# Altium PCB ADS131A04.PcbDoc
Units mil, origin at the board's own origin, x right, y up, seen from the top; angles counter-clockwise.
Board outline 2190 x 1496.06 mil, 2 copper layers (Top Layer, Bottom Layer); 74 components, 47 nets, 208 pads, 279 vias.
Unrouted connection lines stored in the file: 46.
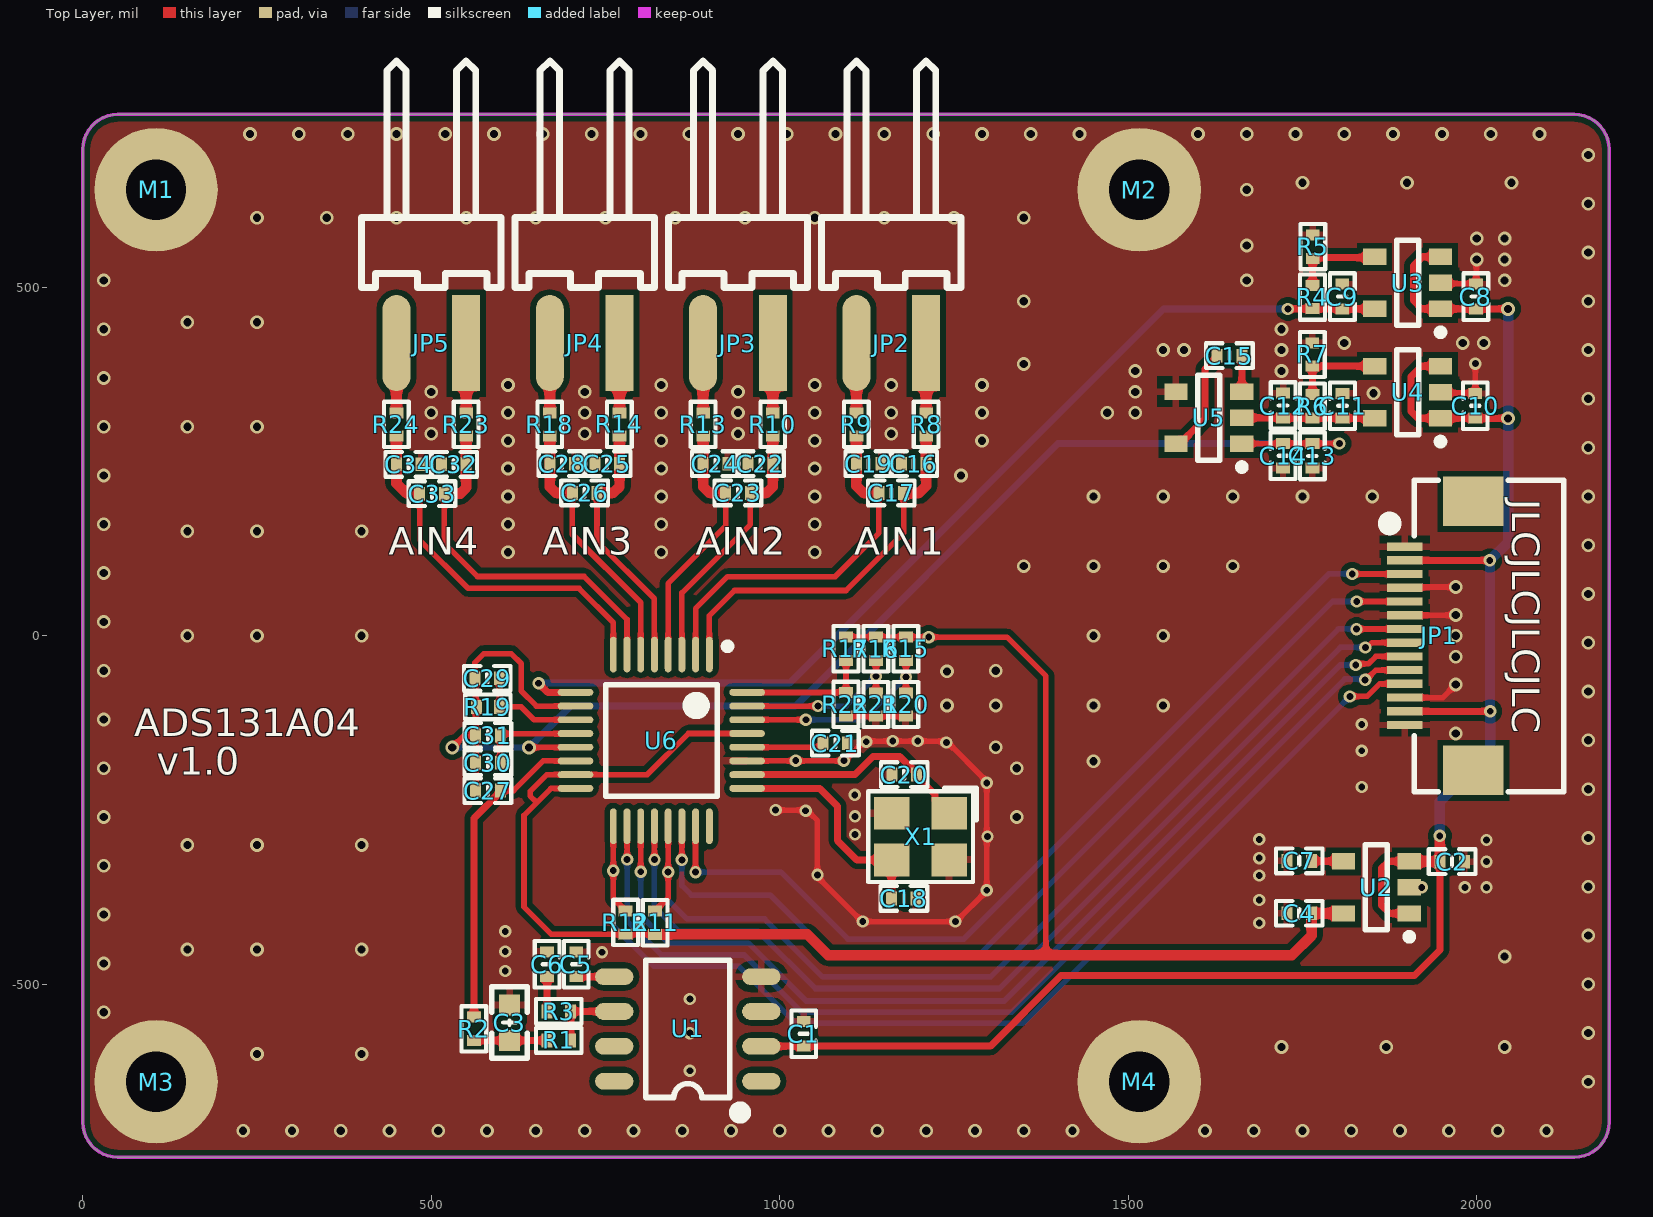
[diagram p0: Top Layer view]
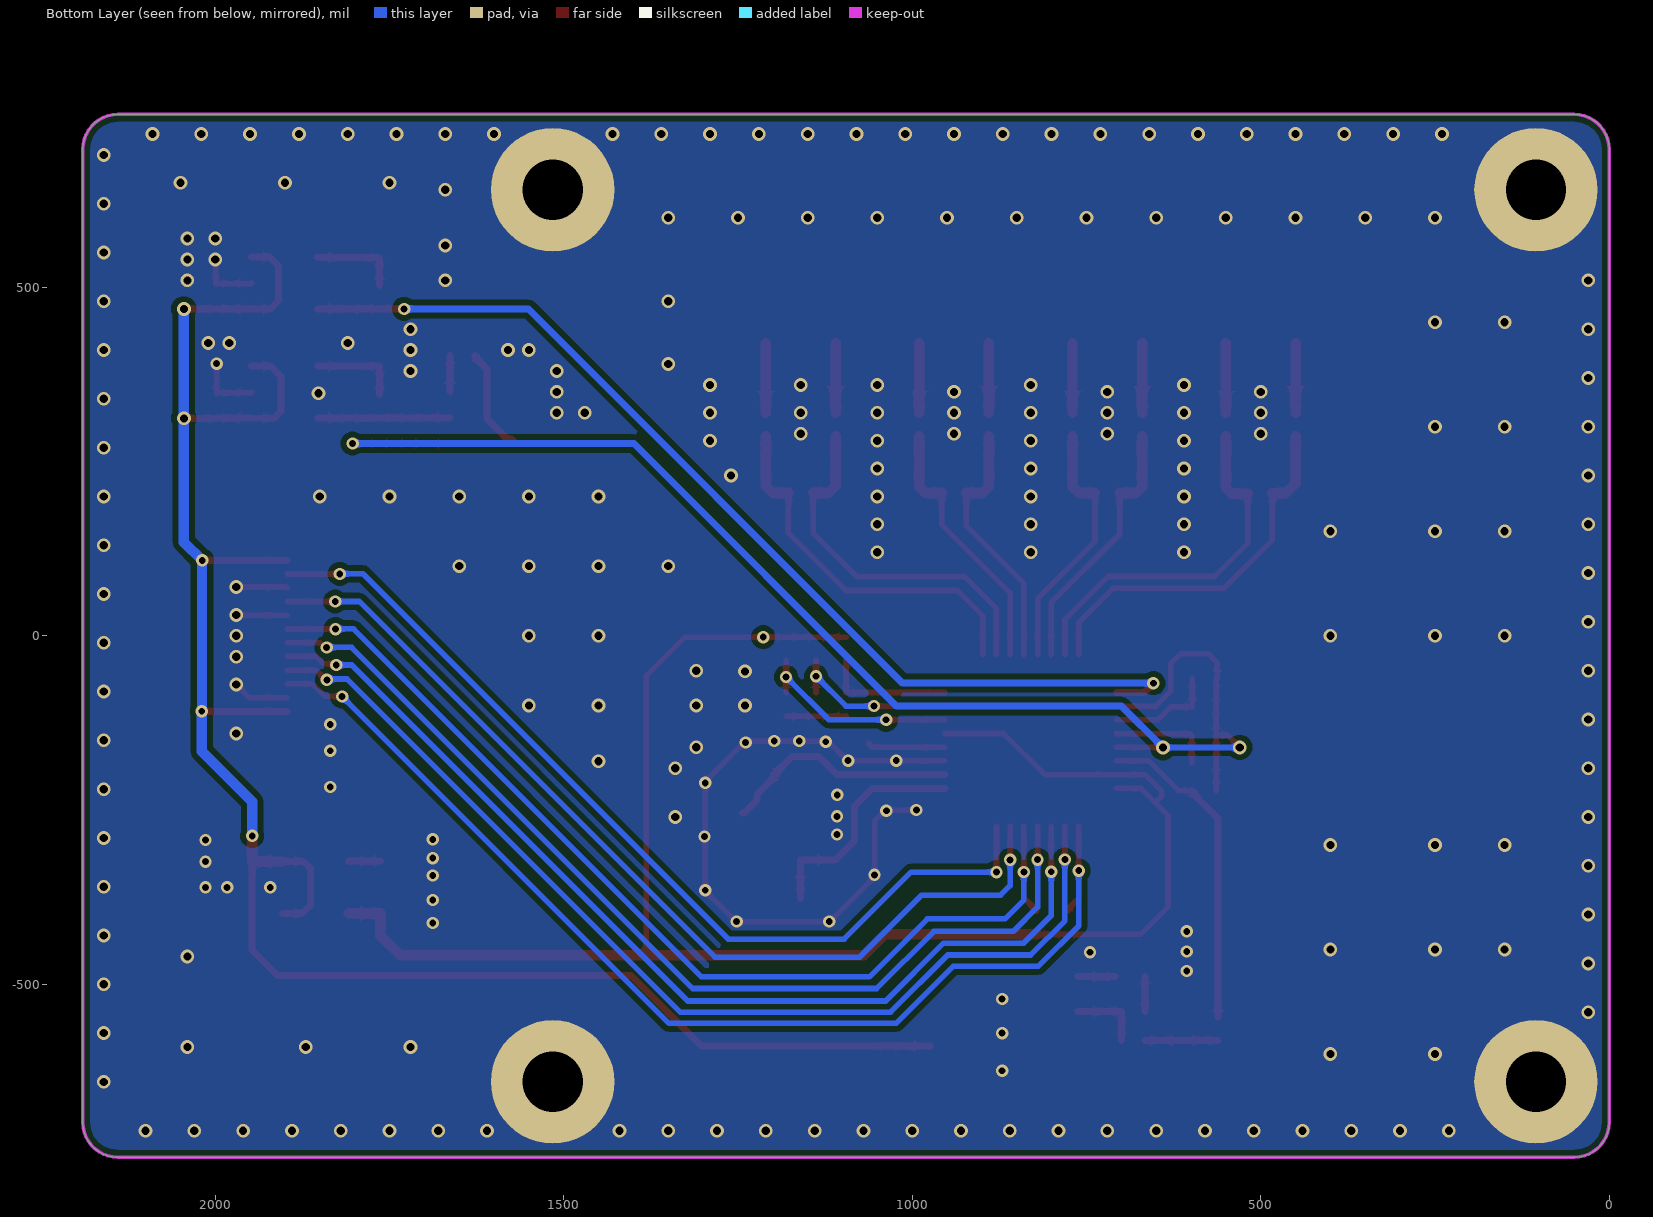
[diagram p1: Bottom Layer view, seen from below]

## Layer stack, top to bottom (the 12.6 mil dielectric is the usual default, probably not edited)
Top Solder: solder mask 0.4, Solder Resist, Dk 3.5
Top Layer: signal copper 1.4
Dielectric 1: dielectric 12.6, FR-4, Dk 4.8
Bottom Layer: signal copper 1.4
Bottom Solder: solder mask 0.4, Solder Resist, Dk 3.5

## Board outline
50,-748.03 cw(c50,-698.03) 0,-698.03 0,698.03 cw(c50,698.03) 50,748.03 2140,748.03 cw(c2140,698.03) 2190,698.03 2190,-698.03 cw(c2140,-698.03) 2140,-748.03

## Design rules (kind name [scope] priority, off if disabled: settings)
Clearance Clearance_1 [InPolygon] p1: gap=8 ignorepadtopadclearanceinfootprint=FALSE
Clearance [All] p2: gap=6 ignorepadtopadclearanceinfootprint=FALSE
MinimumSolderMaskSliver [All] p1: minsoldermaskwidth=0
PolygonConnect M2 [HasFootprint('M2')] p1: connectstyle=Direct reliefconductorwidth=10 reliefentries=4 polygonreliefangle="90 Angle" airgapwidth=10
PolygonConnect [All] p2: thpad.connectstyle=Relief thpad.reliefconductorwidth=10 thpad.reliefentries=4 thpad.polygonreliefangle="90 Angle" thpad.airgapwidth=10 smdpad.connectstyle=Relief smdpad.reliefconductorwidth=10 smdpad.reliefentries=4 smdpad.polygonreliefangle="90 Angle" smdpad.airgapwidth=10 via.connectstyle=Direct via.reliefconductorwidth=10 via.reliefentries=4 via.polygonreliefangle="90 Angle" via.airgapwidth=10
RoutingVias [All] p1: holewidth=9.84 width=17.72 viastyle="Through Hole" minholewidth=9.84 minwidth=17.72 maxholewidth=23.62 maxwidth=31.5
SilkToSilkClearance [All] p1: silktosilkclearance=0
SilkToSolderMaskClearance [IsPad] p1: minsilkscreentomaskgap=0 clearancetoexposedcopper=TRUE
SolderMaskExpansion [IsVia] p1: expansion=4 istentingtop=TRUE useseparateexpansions=TRUE expansionbottom=4 istentingbottom=TRUE
Width [All] p1: maxlimit=50 minlimit=6 preferedwidth=6
27 further rules are at their usual default settings.

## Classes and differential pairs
component class Power: C1 C2 C3 C4 C5 C6 C7 C8 C9 C10 C11 C12 C13 C14 C15 JP1 M1 M2 M3 M4 R1 R2 R3 R4 R5 R6 R7 U1 U2 U3 U4 U5
component class ADS131A04: C16 C17 C18 C19 C20 C21 C22 C23 C24 C25 C26 C27 C28 C29 C30 C31 C32 C33 C34 JP2 JP3 JP4 JP5 R8 R9 R10 R11 R12 R13 R14 R15 R16 R17 R18 R19 R20 R21 R22 R23 R24 U6 X1

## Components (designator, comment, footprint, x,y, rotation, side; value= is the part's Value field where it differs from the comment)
C1 "1uF" C0402_L 1034.42,-570.99 r270 top
C2 "1uF" C0402_L 1964.71,-324 r180 top
C3 "10uF" C0603_L 612.32,-555 r270 top
C4 "1uF" C0402_L 1745.29,-398 r0 top
C5 "1000pF" C0402_L 708,-471.29 r270 top
C6 "1uF" C0402_L 666,-471.29 r270 top
C7 "10nF" C0402_L 1745.29,-323 r0 top
C8 "1uF" C0402_L 1998.79,486.8 r270 top
C9 "1uF" C0402_L 1807.15,486.82 r270 top
C10 "1uF" C0402_L 1997.91,329.99 r270 top
C11 "1uF" C0402_L 1807.39,330.04 r270 top
C12 "0.01uF" C0402_L 1722.04,330.45 r270 top
C13 "1uF" C0402_L 1764.26,258.22 r90 top
C14 "0.01uF" C0402_L 1722.02,258.36 r90 top
C15 "1uF" C0402_L 1645.22,401.99 r180 top
C16 "100pF" C0402_L 1192.29,247 r0 top
C17 "4.7nF" C0402_L 1160,205 r0 top
C18 "30pF" C0402_L 1178.03,-376.82 r0 top
C19 "100pF" C0402_L 1127.72,247 r0 top
C20 "30pF" C0402_L 1178.5,-199.07 r180 top
C21 "1uF" C0402_L 1079.72,-154 r0 top
C22 "100pF" C0402_L 972.29,247 r0 top
C23 "4.7nF" C0402_L 940,205 r0 top
C24 "100pF" C0402_L 907.72,247 r0 top
C25 "100pF" C0402_L 752.29,247 r0 top
C26 "4.7nF" C0402_L 720,205 r0 top
C27 "1uF" C0402_L 581.28,-222 r180 top
C28 "100pF" C0402_L 687.72,247 r0 top
C29 "270nF" C0402_L 580.28,-61 r180 top
C30 "1uF" C0402_L 581.28,-182 r180 top
C31 "0.1uF" C0402_L 581.28,-143 r180 top
C32 "100pF" C0402_L 532.29,246 r0 top
C33 "4.7nF" C0402_L 501,204 r0 top
C34 "100pF" C0402_L 467.72,246 r0 top
JP1 "HDR-1X14" FPC0.5-WT-14P 1995,0 r270 top
JP2 "HDR-1X2" HDR2.54-WS-2P 1160,420 r180 top
JP3 "HDR-1X2" HDR2.54-WS-2P 940,420 r180 top
JP4 "HDR-1X2" HDR2.54-WS-2P 720,420 r180 top
JP5 "HDR-1X2" HDR2.54-WS-2P 500,420 r180 top
M1 "M2" M2 105,640 r0 top
M2 "M2" M2 1515.94,640 r0 top
M3 "M2" M2 105,-640 r0 top
M4 "M2" M2 1515.94,-640 r0 top
R1 "100R" R0402_L 682.91,-580.61 r180 top
R2 "NC/0R" R0402_L 561.24,-563.85 r90 top
R3 "1R" R0402_L 682.84,-538.97 r0 top
R4 "340K/1%" R0402_L 1764.33,486.07 r270 top
R5 "160K/1%" R0402_L 1764.8,558.43 r90 top
R6 "340K/1%" R0402_L 1764.19,329.37 r270 top
R7 "160K/1%" R0402_L 1764.15,403.66 r90 top
R8 "100R" R0402_L 1210,303.27 r270 top
R9 "100R" R0402_L 1110,303.27 r270 top
R10 "100R" R0402_L 989.98,303.27 r270 top
R11 "100K" R0402_L 821.02,-411.64 r270 top
R12 "100K" R0402_L 778.71,-411.26 r270 top
R13 "100R" R0402_L 890,303.27 r270 top
R14 "100R" R0402_L 770,303.27 r270 top
R15 "NC/0R" R0402_L 1181,-18.54 r90 top
R16 "NC/0R" R0402_L 1138,-18.54 r90 top
R17 "NC/0R" R0402_L 1095,-18.54 r90 top
R18 "100R" R0402_L 670,303.27 r270 top
R19 "NC/0R" R0402_L 581.27,-102 r180 top
R20 "NC/0R" R0402_L 1181,-98.54 r90 top
R21 "NC/0R" R0402_L 1138,-98.54 r90 top
R22 "NC/0R" R0402_L 1095,-98.27 r90 top
R23 "100R" R0402_L 550,303.27 r270 top
R24 "100R" R0402_L 450,303.27 r270 top
U1 "REF5025AIDR" SOIC-8L 868,-564 r180 top
U2 "LP2992-3.3" SOT23-5L 1856,-361 r180 top
U3 "SGM2036" SOT23-5L 1900.76,506.4 r180 top
U4 "SGM2036" SOT23-5L 1900.76,349.6 r180 top
U5 "TPS60403" SOT23-5L 1615.69,312.99 r180 top
U6 "ADS131A04" "TQFP32 5x5_L" 830,-150 r180 top
X1 "16.384MHz" XTAL-3225-4P 1202,-288 r180 top

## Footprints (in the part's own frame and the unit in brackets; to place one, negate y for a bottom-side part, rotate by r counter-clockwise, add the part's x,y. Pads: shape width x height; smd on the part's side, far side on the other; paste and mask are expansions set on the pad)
C0402_L [mm] "无极性贴片电容"
  rect 0.4x0.5 smd: 1(-0.45,0) 2(0.45,0)
  silkscreen extent -0.85,-0.45 0.85,0.45, body extent -0.5,-0.26 0.5,0.26, height 0.54
C0603_L [mil] "无极性贴片电容"
  rect 30x30 smd: 1(-25.59,0) 2(25.59,0)
  silkscreen extent -51,-26 51,26, body extent -31,-16 32,16, height 33
FPC0.5-WT-14P [mm] "长：11.2mm，宽：5.2mm，高：2mm"
  rect 1.8x2.2 smd: 0(-4.9,0) 0(4.9,0)
  rect 0.3x1.3 smd: 1(-3.25,-2.497) 2(-2.75,-2.497) 3(-2.25,-2.497) 4(-1.75,-2.497) 5(-1.25,-2.497) 6(-0.75,-2.497) 7(-0.25,-2.497) 8(0.25,-2.497) 9(0.75,-2.497) 10(1.25,-2.497) 11(1.75,-2.497) 12(2.25,-2.497) 13(2.75,-2.497) 14(3.25,-2.497)
  silkscreen extent -5.68,-3.23 5.68,3.3, body extent -5.6,-2.85 5.6,3.15, height 2
HDR2.54-WS-2P [mm] "2P卧式贴片排针2.54"
  rect 1.02x3.5 smd: 1(-1.27,0)
  oval 1.02x3.5 smd: 2(1.27,0)
  silkscreen extent -2.54,-10.29 2.54,-2.03, body extent -2.54,-10.34 2.54,0.76, height 2.59
M2 [mm]
  round 4.5 hole 2.2: 1(0,0)
R0402_L [mm] "1/16W贴片电阻"
  rect 0.4x0.5 smd: 1(-0.425,0) 2(0.425,0)
  silkscreen extent -0.82,-0.45 0.83,0.45, body extent -0.5,-0.25 0.5,0.25, height 0.3
SOIC-8L [mm] "封装库来自淘宝卖家 ID：黄晶宝石，其他均为盗版"
  oval 1.397x0.61 smd: 1(-2.68,1.905) 2(-2.68,0.635) 3(-2.68,-0.635) 4(-2.68,-1.905) 5(2.68,-1.905) 6(2.68,-0.635) 7(2.68,0.635) 8(2.68,1.905)
  silkscreen extent -2.06,-2.5 1.52,3.2, body extent -3,-2.5 3,2.5, height 1.9
SOT23-5L [mm] "SOT23, 5-Leads, Body 2.9x1.6mm, Pitch 0.95mm, IPC High Density"
  rect 0.85x0.6 smd: 1(-1.2,0.95) 2(-1.2,0) 3(-1.2,-0.95) 4(1.2,-0.95) 5(1.2,0.95)
  silkscreen extent -1.33,-1.55 0.4,1.92, body extent -1.4,-1.5 1.4,1.5, height 1.15
"TQFP32 5x5_L" [mm] "32脚，体宽：5x5mm, 脚距：0.5mm          淘宝ID:黄晶宝石"
  oval 0.25x1.3 smd: 1(-1.75,-3.127) 2(-1.25,-3.127) 3(-0.75,-3.127) 4(-0.25,-3.127) 5(0.25,-3.127) 6(0.75,-3.127) 7(1.25,-3.127) 8(1.75,-3.127) 17(1.75,3.127) 18(1.25,3.127) 19(0.75,3.127) 20(0.25,3.127) 21(-0.25,3.127) 22(-0.75,3.127) 23(-1.25,3.127) 24(-1.75,3.127)
  oval 1.3x0.25 smd: 9(3.127,-1.75) 10(3.127,-1.25) 11(3.127,-0.75) 12(3.127,-0.25) 13(3.127,0.25) 14(3.127,0.75) 15(3.127,1.25) 16(3.127,1.75) 25(-3.127,1.75) 26(-3.127,1.25) 27(-3.127,0.75) 28(-3.127,0.25) 29(-3.127,-0.25) 30(-3.127,-0.75) 31(-3.127,-1.25) 32(-3.127,-1.75)
  silkscreen extent -2.54,-3.55 2.03,2.03, body extent -3.5,-3.5 3.5,3.5, height 1.05
XTAL-3225-4P [mm] "3.2*2.5*0.7mm(长宽高)                             淘宝ID:黄晶宝石"
  rect 1.3x1.2 smd: 1(-1.05,-0.85) 2(1.05,-0.85) 3(1.05,0.85) 4(-1.05,0.85)
  silkscreen extent -2.03,-1.75 1.91,1.65, body extent -1.6,-1.25 1.6,1.25, height 0.7

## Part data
C1 C2 C3 C4 C5 C6 C7 C8 C9 C10 C11 C12 C13 C14 C15 C16 C17 C18 C19 C20 C21 C22 C23 C24 C25 C26 C27 C28 C29 C30 C31 C32 C33 C34: library part C, "贴片电容"
JP1: library part "Header 14", "14P接插件"
JP2 JP3 JP4 JP5: library part "Header 2", "2P接插件"
M1 M2 M3 M4: library part M2系列, "M2孔支撑柱"
R1 R2 R3 R4 R5 R6 R7 R8 R9 R10 R11 R12 R13 R14 R15 R16 R17 R18 R19 R20 R21 R22 R23 R24: library part R, "贴片电阻"
U1: "3uVpp/V噪声 3ppm/℃漂移 电压基准 0.05%"
U2: library part LP2992
U3 U4: "可调LDO"
U5: library part TPS6040x, "非稳压60mA电荷泵电压逆变器"
U6: "4通道差分24位ADC"
X1: library part XTAL-4P, "4脚无源晶振(谐振器）"

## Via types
v1: diameter 19.68, hole 11.81, Top Layer to Bottom Layer, tented both sides, 216 vias
v2: diameter 17.72, hole 9.84, Top Layer to Bottom Layer, tented both sides, 63 vias

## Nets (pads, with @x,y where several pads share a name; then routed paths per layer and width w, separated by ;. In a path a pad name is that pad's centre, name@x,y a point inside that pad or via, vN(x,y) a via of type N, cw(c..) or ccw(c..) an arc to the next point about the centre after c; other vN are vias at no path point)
+2V5: C9.2 R4.2 U3.5 U6.9 | length 1480.5
  Top Layer w10: v2(654,-68) 667.1,-81.1 U6.9 ; v2(1729,469) 1729.17,469.17 1764.16,469.17 R4.2 1764.45,469.22 1807.03,469.22 C9.2 1807.2,469.05 1853.46,469.05 U3.5
  Bottom Layer w10: v2(654,-68) 1013.78,-68 1550.78,469 v2(1729,469)
-2V5: C13.2 C14.2 C27.2 C29.2 C30.2 C31.2 R19.2 U5.1 U6.10 U6.13 | length 2090.2
  Top Layer w8: v1(530.16,-160.16) 547.8,-142.51 C31.2@564.05,-142.51 ; C27.2 C30.2 C31.2 C31.2@564.05,-142.51 ; v1(640.16,-160.35) 640.41,-160.1 706.63,-160.1 U6.13 ; U6.10 650.79,-100.79 629,-79 629,-40 614.82,-25.82 575.13,-25.82 562.57,-38.38 C29.2 563.55,-61.98 563.55,-101.02 R19.2 564.05,-102.48 C31.2@564.05,-142.51 ; U5.1 1663.18,275.83 1721.78,275.83 C14.2 1722.09,276 1764.2,276 C13.2 v2(1802.93,275.93)
  Bottom Layer w8: v1(530.16,-160.16) 530.25,-160.26 640.06,-160.26 v1(640.16,-160.35)
  Bottom Layer w10: v1(640.16,-160.35) 699.51,-101 1022.27,-101 1399.21,275.93 v2(1802.93,275.93)
ADS_CS: JP1.3 U6.23 | length 1340.8
  Top Layer w8: v2(879,-339) 879.11,-338.89 879.11,-273.22 U6.23 ; v2(1821.47,88.79) 1821.57,88.69 1896.59,88.69 JP1.3
  Bottom Layer w8: v2(879,-339) 1001.68,-339 1097.8,-435.12 1264,-435.12 1788.12,89 1821.26,89 v2(1821.47,88.79)
ADS_DIN: JP1.8 U6.20 | length 1446.5
  Top Layer w8: v2(820.16,-321.16) U6.20 ; v2(1840.18,-16.7) 1842.81,-16.7 1849.67,-9.84 JP1.8
  Bottom Layer w8: v2(820.16,-321.16) 820.16,-389.16 855,-424 969,-424 1051,-506 1315,-506 1804.3,-16.7 v2(1840.18,-16.7)
ADS_DONE: JP1.10 U6.18 | length 1510.3
  Top Layer w8: U6.18 781,-273.32 780.89,-273.43 780.89,-320.89 v2(781,-321) ; v2(1839.82,-63.18) 1841.38,-63.18 1855.35,-49.21 JP1.10
  Bottom Layer w8: v2(781,-321) 781,-409 830,-458 949,-458 1031,-540 1333,-540 1811,-62 1838.64,-62 v2(1839.82,-63.18)
ADS_DOUT: JP1.7 R11.1 U6.21 | length 1480.3
  Top Layer w8: R11.1 822.99,-394.9 826.87,-391.03 826.87,-389.06 839.84,-376.08 v2(839.84,-338.84) U6.21 ; v2(1827.49,9.67) 1827.58,9.76 1896.61,9.76 JP1.7
  Bottom Layer w8: v2(839.84,-338.84) 839.84,-378.94 867.03,-406.12 978.31,-406.12 1061.49,-489.3 1302.5,-489.3 1801.64,9.84 1827.32,9.84 v2(1827.49,9.67)
ADS_DRDY: JP1.9 U6.19 | length 1480.2
  Top Layer w8: v2(800.47,-338.47) U6.19 ; v2(1826.46,-41.91) 1828.32,-40.05 1844.71,-40.05 1855.24,-29.53 JP1.9
  Bottom Layer w8: v2(800.47,-338.47) 800.47,-401.47 840,-441 955,-441 1038,-524 1322,-524 1804.09,-41.91 v2(1826.46,-41.91)
ADS_RESET: JP1.11 R12.1 U6.17 | length 1604.2
  Top Layer w8: U6.17 v2(761.1,-336.9) 761.1,-376.92 772.87,-388.69 772.87,-390.66 776.74,-394.53 R12.1 ; v2(1818,-87) 1842.66,-87 1860.66,-69.01 JP1.11@1896.58,-69.01
  Bottom Layer w8: v2(761.1,-336.9) 761.1,-416.1 819,-474 941,-474 1023,-556 1349,-556 v2(1818,-87)
ADS_SCLK: JP1.5 U6.22 | length 1376.5
  Top Layer w8: v2(859.53,-321.53) U6.22 ; v2(1827.86,49.3) v2(1827.86,49.3) 1896.65,49.25 JP1.5
  Bottom Layer w8: v2(859.53,-321.53) 859.53,-358.53 873.1,-372.09 986.28,-372.09 1075.29,-461.1 1282.91,-461.1 1793.31,49.3 v2(1827.86,49.3)
AIN1N: C16.2 C17.2 R8.2 U6.1 | length 549.1
  Top Layer w8: U6.1 898.9,28.9 935,65 1095,65 1177.71,147.71 C17.2
  Top Layer w15: C17.2 1200,205 1210,215 C16.2 R8.2
AIN1P: C17.1 C19.1 R9.2 U6.2 | length 539.3
  Top Layer w8: U6.2 879.21,39.21 925,85 1079.54,85 1142.28,147.74 C17.1
  Top Layer w15: R9.2 C19.1 1110,215 1120,205 C17.1
AIN2N: C22.2 C23.2 R10.2 U6.3 | length 381.2
  Top Layer w8: U6.3 859.53,61.53 957.71,159.71 C23.2
  Top Layer w15: C23.2 981.2,205 989.99,213.78 C22.2 R10.2
AIN2P: C23.1 C24.1 R13.2 U6.4 | length 374.6
  Top Layer w8: U6.4 839.84,74.84 922.28,157.28 C23.1
  Top Layer w15: R13.2 C24.1 890,214 899,205 C23.1
AIN3N: C25.2 C26.2 R14.2 U6.5 | length 374.6
  Top Layer w8: C26.2 737.71,135.59 820.16,53.14 U6.5
  Top Layer w15: C26.2 761,205 770,214 C25.2 R14.2
AIN3P: C26.1 C28.1 R18.2 U6.6 | length 381.2
  Top Layer w8: C26.1 702.28,145.72 800.47,47.53 U6.6
  Top Layer w15: R18.2 670,213.79 678.79,205 C26.1
AIN4N: C32.2 C33.2 R23.2 U6.7 | length 537.7
  Top Layer w8: C33.2 518.71,132.75 566.32,85.14 719.17,85.14 780.79,23.53 U6.7
  Top Layer w15: C33.2 541.21,204 550,212.78 C32.2 R23.2
AIN4P: C33.1 C34.1 R24.2 U6.8 | length 546.3
  Top Layer w8: C33.1 483.28,137.72 553,68 712,68 761.1,18.9 U6.8
  Top Layer w15: R24.2 450,219 464.37,204.63 482.91,204.63 483.28,204.25 C33.1
GND: C1.1 C2.1 C3.1 C4.1 C5.1 C6.1 C7.1 C8.1 C9.1 C10.1 C11.1 C12.1 C13.1 C14.1 C16.1 C18.2 C19.2 C20.2 C21.2 C22.1 C24.2 C25.1 C28.2 C32.1 C34.2 JP1.1 JP1.4 JP1.6 JP1.12 JP1.14 M1.1 M2.1 M3.1 M4.1 R5.2 R7.2 R20.1 R21.1 R22.1 U1.4 U2.2 U3.2 U4.2 U5.4 U6.27 X1.2 X1.4 | length 1467.2
  Top Layer w8: U6.27 1092.47,-179.53 1121,-151 1239,-151 1297,-209 1297,-366 1253,-410 1118,-410 1054,-346 1054,-265 1039,-250 v2(994,-250) ; R22.1 1095.13,-115.13 1137.87,-115.13 R21.1 R20.1 ; JP1.12 1951.42,-88.58 v1(1970,-70) ; JP1.6 1969.53,29.53 v1(1970,30) ; JP1.4 1897.79,70 v1(1970,70) ; U4.2 1948.95,348.65 1996.96,348.65 C10.1 1997.96,347.76 v2(1998.01,390.6) v2(1998.01,390.6) ; U3.2 1948.94,505.46 1997.84,505.46 C8.1 1999.39,505.12 1999.39,539.39 v1(2000,540)
  other v1: 230,-710 300,-710 370,-710 440,-710 510,-710 580,-710 650,-710 720,-710 790,-710 860,-710 930,-710 1000,-710 1070,-710 1140,-710 1210,-710 1280,-710 1350,-710 1420,-710 1610,-710 1680,-710 1750,-710 1820,-710 1890,-710 1960,-710 2030,-710 2100,-710 2160,-640 250,-600 400,-600 1720,-590 1870,-590 2040,-590 2160,-570 30,-540 2160,-500 30,-470 2040,-460 150,-450 250,-450 400,-450 2160,-430 30,-400 2160,-360 30,-330 150,-300 250,-300 400,-300 2160,-290 30,-260 1340,-260 2160,-220 30,-190 1340,-190 1450,-180 1310,-160 2160,-150 1970,-140 30,-120 1240,-100 1310,-100 1450,-100 1550,-100 2160,-80 1240,-51 30,-50 1310,-50 1970,-30 2160,-10 150,0 250,0 400,0 1450,0 1550,0 1970,0 30,20 2160,60 30,90 1350,100 1450,100 1550,100 1650,100 610,120 830,120 1050,120 2160,130 150,150 250,150 400,150 30,160 610,160 830,160 1050,160 610,200 830,200 1050,200 1450,200 1550,200 1650,200 1750,200 1850,200 2160,200 30,230 1260,230 610,240 830,240 1050,240 2160,270 610,280 830,280 1050,280 1290,280 500,290 720,290 940,290 1160,290 30,300 150,300 250,300 500,320 610,320 720,320 830,320 940,320 1050,320 1160,320 1290,320 1470,320 1510,320 2160,340 1852,348 500,350 720,350 940,350 1510,350 610,360 830,360 1050,360 1160,360 1290,360 30,370 1510,380 1720,380 1350,390 1550,410 1580,410 1720,410 2160,410 1810,420 1980,420 2010,420 30,440 1720,440 150,450 250,450 1350,480 2160,480 30,510 1670,510 2040,510 2040,540 2160,550 1670,560 2000,570 2040,570 250,600 350,600 450,600 550,600 650,600 750,600 850,600 950,600 1050,600 1150,600 1250,600 1350,600 2160,620 1670,640 1750,650 1900,650 2050,650 2160,690 240,720 310,720 380,720 450,720 520,720 590,720 660,720 730,720 800,720 870,720 940,720 1010,720 1080,720 1150,720 1220,720 1290,720 1360,720 1430,720 1600,720 1670,720 1740,720 1810,720 1880,720 1950,720 2020,720 2090,720
  other v2: 871,-624 871,-570 871,-521 606,-481 745,-454 606,-453 606,-424 1688,-412 1119,-410 1252,-410 1688,-379 1297,-365 1921,-361 1983,-361 2014,-361 1688,-344 1054,-343 2014,-324 1688,-319 2014,-293 1688,-292 1298,-288 1108,-285 1108,-259 1037,-251 1107.56,-228.26 1835,-217 1297,-211 1023,-179 1092,-179 1835,-165 1239,-153 1124,-152 1162,-151 1198,-151 1835,-127
M0: R15.1 R20.2 U6.30 | length 299.9
  Top Layer w8: U6.30 v2(1037.47,-120.47) ; R20.2 v2(1181,-59) R15.1
  Bottom Layer w8: v2(1037.47,-120.47) 1119.53,-120.47 v2(1181,-59)
M1: R16.1 R21.2 U6.31 | length 249.1
  Top Layer w8: U6.31 v2(1054.79,-100.79) ; R21.2 v2(1138,-58) R16.1
  Bottom Layer w8: v2(1054.79,-100.79) 1095.21,-100.79 v2(1138,-58)
M2: R17.1 R22.2 U6.32 | length 188.3
  Top Layer w8: U6.32 953.33,-81.32 1094.78,-81.32 R22.2 R17.1
NetC3_2: C3.2 R1.2 R2.1 | length 105
  Top Layer w10: R2.1 C3.2 ; C3.2 R1.2
NetC5_2: C5.2 U1.5 | length 54.5
  Top Layer w10: C5.2 U1.5
NetC6_2: C6.2 R3.1 | length 50
  Top Layer w10: C6.2 666.05,-489.05 666.05,-538.92 R3.1
NetC7_2: C7.2 U2.4 | length 46
  Top Layer w10: C7.2 1763.3,-323.3 1808.46,-323.3 U2.4
NetC15_1: C15.1 U5.3 | length 51.6
  Top Layer w10: U5.3 C15.1
NetC15_2: C15.2 U5.5 | length 154.2
  Top Layer w10: U5.5 1575.26,282.39 1580.94,282.39 1610,311.46 1610,382.51 1627.51,400.02 C15.2
NetC21_1: C21.1 U6.28 | length 112.5
  Top Layer w8: U6.28 1058.13,-159.84 1062,-155.97 C21.1
NetC29_1: C29.1 R19.1 U6.11 | length 157.5
  Top Layer w8: C29.1 R19.1 629,-102 647.47,-120.47 U6.11
NetC30_1: C30.1 C31.1 U6.12 | length 148.1
  Top Layer w8: C30.1 C31.1 601.49,-140.51 706.54,-140.51 U6.12
NetJP2_1: JP2.1 R8.1 | length 100
  Top Layer w15: R8.1 JP2.1
NetJP2_2: JP2.2 R9.1 | length 100
  Top Layer w15: R9.1 JP2.2
NetJP3_1: JP3.1 R10.1 | length 100
  Top Layer w15: R10.1 JP3.1
NetJP3_2: JP3.2 R13.1 | length 100
  Top Layer w15: R13.1 JP3.2
NetJP4_1: JP4.1 R14.1 | length 100
  Top Layer w15: R14.1 JP4.1
NetJP4_2: JP4.2 R18.1 | length 100
  Top Layer w15: R18.1 JP4.2
NetJP5_1: JP5.1 R23.1 | length 100
  Top Layer w15: R23.1 JP5.1
NetJP5_2: JP5.2 R24.1 | length 100
  Top Layer w15: R24.1 JP5.2
NetR1_1: R1.1 R3.2 U1.6 | length 104.6
  Top Layer w10: R1.1 R1.1 R3.2 U1.6
NetR4_1: R4.1 R5.1 U3.4 | length 128.7
  Top Layer w10: R4.1 1764.57,503.03 1764.57,541.47 R5.1 1765.85,542.75 1852.46,542.75 U3.4
NetR6_1: R6.1 R7.1 U4.4 | length 130.2
  Top Layer w10: R6.1 R7.1@1764.17,386.91 ; R7.1 1764.19,386.96 U4.4 U4.4
VCC_2V5: C11.2 C12.2 R6.2 U4.5 U5.2 | length 190.9
  Top Layer w10: U5.2 1663.06,312.86 1721.91,312.86 C12.2 1722.08,312.69 1764.15,312.69 R6.2 1764.35,312.48 1807.23,312.48 C11.2 1807.45,312.26 1853.45,312.26 U4.5
VCC_3V3: C4.2 R11.2 R12.2 R15.2 R16.2 R17.2 U2.5 U6.15 U6.16 U6.29 | length 2586.9
  Top Layer w8: 650.71,-238.76 641.79,-229.84 641.79,-223.21 665.79,-199.21 U6.15 809.79,-199.21 868.84,-140.16 U6.29 ; 671.7,-218.9 633,-257.6 633,-389 672.37,-428.37 R11.2 820.84,-428.18 778.9,-428.18 R12.2 ; 672.5,-218.9 U6.16 ; R17.2 R16.2 R15.2 v2(1213.8,-1.8) 1325.8,-1.8 1381.72,-57.72 1381.72,-458.34 ; C4.2 C4.2@1763.2,-398.2 ; U2.5@1808.56,-398.2 U2.5
  Top Layer w15: R11.2 1039.37,-428.37 1069.34,-458.34 1381.72,-458.34 1734.66,-458.34 1763,-430 C4.2 ; C4.2@1763.2,-398.2 U2.5@1808.56,-398.2
VCC_5V: C1.2 C2.2 C8.2 C10.2 JP1.2 JP1.13 U1.2 U2.1 U2.3 U3.1 U3.3 U4.1 U4.3 | length 2899.1
  Top Layer w10: U1.2 973.66,-588.85 C1.2@1034.26,-588.85 ; C1.2 C1.2@1034.26,-588.85 ; JP1.13 v2(2019.32,-108.27) ; JP1.2 v2(2018.73,108.27) ; U2.1 1875.4,-398.4 1863,-386 1863,-334 1873.4,-323.6 U2.3 U2.3@1903.44,-323.8 ; C2.2@1946.8,-323.8 C2.2 1947,-450.83 1910.39,-487.44 1403.56,-487.44 1302.15,-588.85 C1.2@1034.26,-588.85 ; U4.3 1921,387 1906,372 1906,322 1915.8,312.2 U4.1 U4.1 1997.86,312.24 C10.2 1998.04,312.14 2044.86,312.14 v1(2045,312) ; U3.3 1921.8,543.8 1909,531 1909,481 1921,469 U3.1 U3.1 1998.74,469.04 C8.2 1998.82,469.04 v1(2045,469) v1(2045,469)
  Top Layer w15: U2.3@1903.44,-323.8 C2.2@1946.8,-323.8 ; C2.2 v2(1947,-287)
  Bottom Layer w15: v2(1947,-287) 1947,-238 2019.32,-165.68 v2(2019.32,-108.27) 2019.02,-107.97 2019.02,107.98 v2(2018.73,108.27) 2045,134.54 v1(2045,312) v1(2045,469)
VREF: C27.1 R2.2 U6.14 | length 466.2
  Top Layer w8: C27.1 618,-222 660.47,-179.53 U6.14
  Top Layer w10: R2.2 561.24,-261.73 599,-223.97 C27.1
XTAL1: C18.1 U6.25 X1.3 | length 334.5
  Top Layer w8: X1.3@1160.31,-321.82 X1.3
  Top Layer w10: U6.25 1057.35,-218.9 1083,-244.55 1083,-294 1110.46,-321.46 X1.3 ; C18.1 X1.3@1160.31,-321.82
XTAL2: C20.1 U6.26 X1.1 | length 342.1
  Top Layer w10: U6.26 1107.79,-199.21 1134,-173 1172.12,-173 1196.22,-197.1 C20.1 1196.22,-201.04 1222.75,-227.57 1222.75,-235.91 1241.37,-254.54 X1.1
pads on no net: JP1.0 U1.1 U1.3 U1.7 U1.8 U6.24

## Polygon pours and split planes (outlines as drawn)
GND on Top Layer "GND_L01_P000" (solid, remove dead copper, pour order 0): -4,752 -4,-753 2193,-753 2193,752
GND on Bottom Layer "GND_L02_P001" (solid, remove dead copper, pour order 1): -4,752 -4,-753 2193,-753 2193,752

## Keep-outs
Keep-Out Layer:
  lines w5: 0,-698.03 ccw(c50,-698.03) 50,-748.03 2140,-748.03 ccw(c2140,-698.03) 2190,-698.03 2190,698.03 ccw(c2140,698.03) 2140,748.03 1930,748.03 50,748.03 ccw(c50,698.03) 0,698.03 0,-698.03

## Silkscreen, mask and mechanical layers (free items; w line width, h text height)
Top Overlay:
  text "JLCJLCJLCJLC" at 2051,196.1 h40 r270
  text "AIN4" at 438.77,116 h40
  text "AIN3" at 659.73,116 h40
  text "AIN2" at 879.73,116 h40
  text "AIN1" at 1107.06,116 h40
  text "ADS131A04" at 73.9,-144 h40
  text "v1.0" at 106.37,-199 h40
Top Solder:
  region: -0.26,640 cw(c0.01,640) -0.25,640.03 cw(c0.01,640.06) -0.26,640.06 -0.26,640 ccw(c0.01,640) 0.01,639.74 50,639.74 ccw(c50,640) 50.26,640 cw(c100,640) 100,689.74 2080,689.74 cw(c2080,640) 2129.73,640 2129.73,-640 ccw(c2130,-640) 2130,-640.26 2189.87,-640.26 ccw(c2190,-640.04) 2190.27,-640.04 2190.27,-640 ccw(c2190,-640) 2190.27,-639.95 2190.27,698.03 ccw(c2140,698.03) 2140,748.3 50,748.3 ccw(c50,698.03) -0.27,698.03 ccw(c0,698.03) -0.26,697.96
  region: 50,-748.3 cw(c50,-698.03) -0.27,-698.03 -0.27,698.03 cw(c0,698.03) 0.26,698.03 0.26,640.26 50,640.26 cw(c50,640) 50.26,640 50.26,-640 ccw(c100,-640) 100,-689.74 2080,-689.74 ccw(c2080,-640) 2129.73,-640 cw(c2130,-640) 2130,-639.74 2189.74,-639.74 2189.74,698.03 cw(c2190,698.03) 2190.27,698.03 2190.27,-639.95 cw(c2190,-640) 2190.27,-640 cw(c2190,-640) 2190.27,-640.05 2190.27,-698.03 cw(c2140,-698.03) 2140,-748.3
Bottom Solder:
  region: -0.26,640 cw(c0.01,640) -0.25,640.03 cw(c0.01,640.06) -0.26,640.06 -0.26,640 ccw(c0.01,640) 0.01,639.74 50,639.74 ccw(c50,640) 50.26,640 cw(c100,640) 100,689.74 2080,689.74 cw(c2080,640) 2129.73,640 2129.73,-640 ccw(c2130,-640) 2130,-640.26 2189.87,-640.26 ccw(c2190,-640.04) 2190.27,-640.04 2190.27,-640 ccw(c2190,-640) 2190.27,-639.95 2190.27,698.03 ccw(c2140,698.03) 2140,748.3 50,748.3 ccw(c50,698.03) -0.27,698.03 ccw(c0,698.03) -0.26,697.96
  region: 50,-748.3 cw(c50,-698.03) -0.27,-698.03 -0.27,698.03 cw(c0,698.03) 0.26,698.03 0.26,640.26 50,640.26 cw(c50,640) 50.26,640 50.26,-640 ccw(c100,-640) 100,-689.74 2080,-689.74 ccw(c2080,-640) 2129.73,-640 cw(c2130,-640) 2130,-639.74 2189.74,-639.74 2189.74,698.03 cw(c2190,698.03) 2190.27,698.03 2190.27,-639.95 cw(c2190,-640) 2190.27,-640 cw(c2190,-640) 2190.27,-640.05 2190.27,-698.03 cw(c2140,-698.03) 2140,-748.3
Mechanical 1:
  lines w5: 0,-698.03 ccw(c50,-698.03) 50,-748.03 2140,-748.03 ccw(c2140,-698.03) 2190,-698.03 2190,698.03 ccw(c2140,698.03) 2140,748.03 1930,748.03 50,748.03 ccw(c50,698.03) 0,698.03 0,-698.03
